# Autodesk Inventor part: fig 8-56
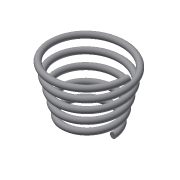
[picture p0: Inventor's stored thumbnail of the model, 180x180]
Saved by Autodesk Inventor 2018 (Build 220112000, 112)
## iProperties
Shininess: 77.0
Length Units: 11269
Angle Units: 11279
Time Units: 11290
Mass Units: 11283
Length Display Precision: 3
Angle Display Precision: 2
Created: 2002-01
Part Number: fig 8-56
Document SubType Name: Modeling
Designer: CADSoft
Density: 1 g/cm^3
Material: Generic
Appearance: Default
Density: 0.0
Volumn: 0.0
Area: 0.0
PropertySet Name: Model Information
Control State: 0
Master: False
Checked Out: False
Author: CADSoft
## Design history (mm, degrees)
sketch "Sketch2"
  geometry: C1 r 2.5 at (-19.895, -0.092)
  constraints: 1 centre point
  dimensions: "d0" = 5 diameter of C1
coil "Coil5" sketch "Sketch2" pitch "d35" = 10; turns "d37" = 5; dims "d36" = 10, "d38" = 15 deg, angle "d39" = 90 deg, angle "d40" = 90 deg, "d41" = 0, "d42" = 0
body "Solid1"
